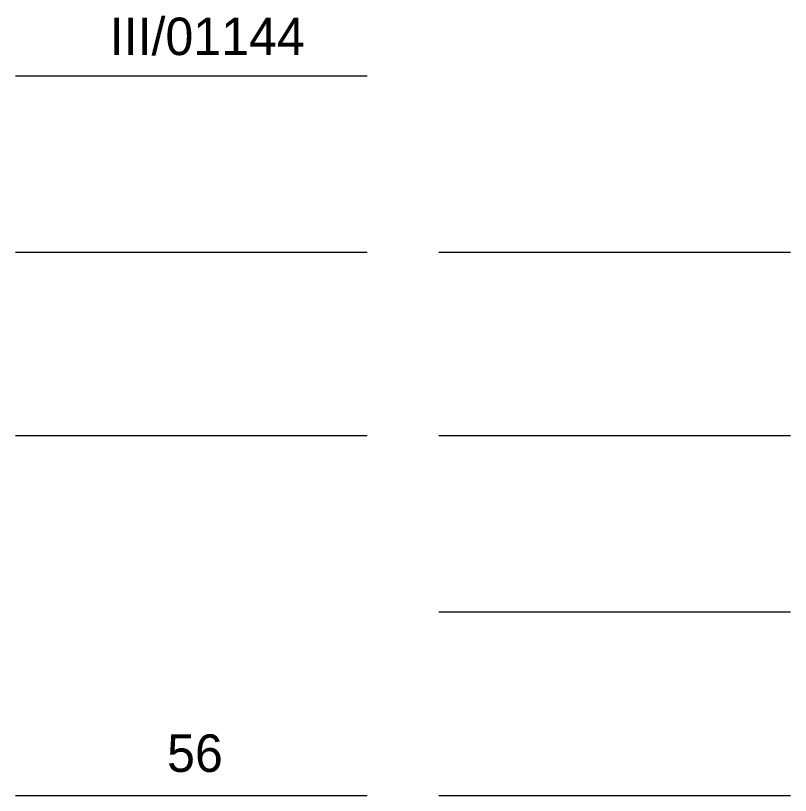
# Model space of a CAD drawing. Extents: x -444937 to -440733, y -1145714 to -1129798.
# Drawn here: x -442269.2 to -442040, y -1145401 to -1145170.4 of the extents above; entities that cross this region are included whole.
import ezdxf

# ---------------------------------------------------------------- set-up
doc = ezdxf.new("R2010")
doc.units = 0
for name, color, linetype in [('Vrstva 12', 7, 'Continuous'), ('Vrstva 7', 7, 'Continuous'), ('Vrstva 75', 7, 'Continuous'), ('Vrstva 76', 7, 'Continuous'), ('Vrstva 8', 7, 'Continuous')]:
    doc.layers.add(name, color=color, linetype=linetype)

msp = doc.modelspace()

# ---------------------------------------------------------------- linework, layer by layer
at = {"layer": 'Vrstva 12'}
for p, q in [((-442269.16, -1145294.6), (-442165.16, -1145294.6)), ((-442269.16, -1145294.6), (-442165.16, -1145294.6)), ((-442269.16, -1145294.6), (-442165.16, -1145294.6)), ((-442143.97, -1145294.6), (-442039.97, -1145294.6)), ((-442143.97, -1145294.6), (-442039.97, -1145294.6)), ((-442143.97, -1145294.6), (-442039.97, -1145294.6))]:
    msp.add_line(p, q, dxfattribs=at)
at = {"layer": 'Vrstva 7'}
msp.add_line((-442269.16, -1145188.25), (-442165.16, -1145188.25), dxfattribs=at)
msp.add_line((-442269.16, -1145188.25), (-442165.16, -1145188.25), dxfattribs=at)
msp.add_line((-442269.16, -1145188.25), (-442165.16, -1145188.25), dxfattribs=at)
at = {"layer": 'Vrstva 75'}
for p, q in [((-442269.16, -1145400.96), (-442165.16, -1145400.96)), ((-442269.16, -1145400.96), (-442165.16, -1145400.96)), ((-442269.16, -1145400.96), (-442165.16, -1145400.96)), ((-442143.97, -1145400.96), (-442039.97, -1145400.96)), ((-442143.97, -1145400.96), (-442039.97, -1145400.96)), ((-442143.97, -1145400.96), (-442039.97, -1145400.96))]:
    msp.add_line(p, q, dxfattribs=at)
at = {"layer": 'Vrstva 76'}
msp.add_line((-442143.97, -1145346.69), (-442039.97, -1145346.69), dxfattribs=at)
msp.add_line((-442143.97, -1145346.69), (-442039.97, -1145346.69), dxfattribs=at)
msp.add_line((-442143.97, -1145346.69), (-442039.97, -1145346.69), dxfattribs=at)
at = {"layer": 'Vrstva 8'}
for p, q in [((-442269.16, -1145240.34), (-442165.16, -1145240.34)), ((-442269.16, -1145240.34), (-442165.16, -1145240.34)), ((-442269.16, -1145240.34), (-442165.16, -1145240.34)), ((-442143.97, -1145240.34), (-442039.97, -1145240.34)), ((-442143.97, -1145240.34), (-442039.97, -1145240.34)), ((-442143.97, -1145240.34), (-442039.97, -1145240.34))]:
    msp.add_line(p, q, dxfattribs=at)

# ---------------------------------------------------------------- texts
at = {"layer": 'Vrstva 7'}
msp.add_text('III/01144', height=11.085, dxfattribs=at).set_placement((-442241.31, -1145182.11))
msp.add_text('III/01144', height=11.085, dxfattribs=at).set_placement((-442241.31, -1145182.11))
msp.add_text('III/01144', height=11.085, dxfattribs=at).set_placement((-442241.31, -1145182.11))
at = {"layer": 'Vrstva 75'}
msp.add_text('56', height=11.085, dxfattribs=at).set_placement((-442224.35, -1145394.01))
msp.add_text('56', height=11.085, dxfattribs=at).set_placement((-442224.35, -1145394.01))
msp.add_text('56', height=11.085, dxfattribs=at).set_placement((-442224.35, -1145394.01))

doc.saveas('drawing.dxf')
